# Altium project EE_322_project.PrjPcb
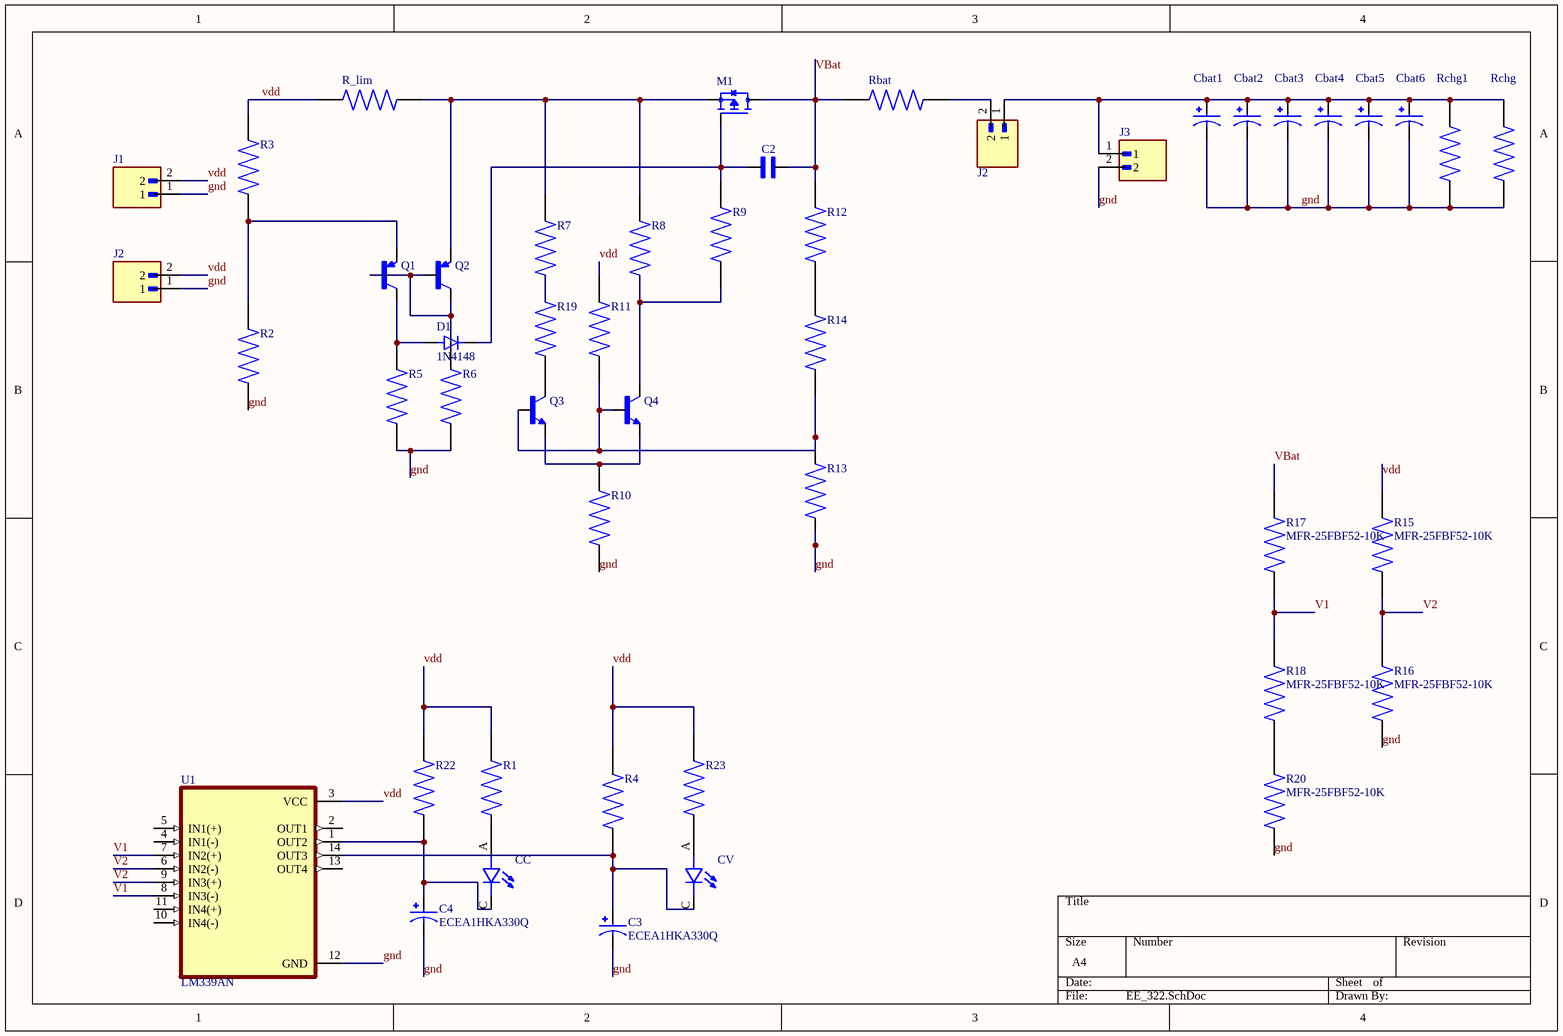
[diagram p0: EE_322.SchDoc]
1 sheet, 48 parts. Net scope: global (net labels, ports and power ports of the same name join across sheets).
Board file: EE322.PcbDoc

## Sheet EE_322.SchDoc
size A4; SheetNumber: 1; SheetTotal: 1

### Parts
(Parts that share a designator on the sheet are numbered #1, #2 ... from top to bottom, then left to right.)
C2  (no value)  [CAPRR254W50L508T317H508]
C3  ECEA1HKA330Q  [CAPPRD500W45D800H700]
C4  ECEA1HKA330Q  [CAPPRD500W45D800H700]
Cbat1  (no value)  [CAPPRD750W80D1600H3150]
Cbat2  (no value)  [CAPPRD750W80D1600H3150]
Cbat3  (no value)  [CAPPRD750W80D1600H3150]
Cbat4  (no value)  [CAPPRD750W80D1600H3150]
Cbat5  (no value)  [CAPPRD750W80D1600H3150]
Cbat6  (no value)  [CAPPRD750W80D1600H3150]
CC  (no value)  [LEDRD254W57D500H1070]
CV  (no value)  [LEDRD254W57D500H1070]
D1  1N4148  [DIOAD753W49L380D172B]
J1  (no value)  [CONNFLY_DS1021-1X2SF11-B]
J2#1  (no value)  [CONNFLY_DS1021-1X2SF11-B]
J2#2  (no value)  [CONNFLY_DS1021-1X2SF11-B]
J3  (no value)  [CONNFLY_DS1021-1X2SF11-B]
M1  (no value)  [TO254P1052X465X1989-3]
Q1  (no value)  [TO92254P460H750-3]
Q2  (no value)  [TO92254P460H750-3]
Q3  (no value)  [TO92254P460H750-3]
Q4  (no value)  [TO92254P460H750-3]
R1  (no value)  [RESAD1100W55L680D260]
R2  (no value)  [RESAD1100W55L680D260]
R3  (no value)  [RESAD1100W55L680D260]
R4  (no value)  [RESAD1100W55L680D260]
R5  (no value)  [RESAD1100W55L680D260]
R6  (no value)  [RESAD1100W55L680D260]
R7  (no value)  [RESAD1100W55L680D260]
R8  (no value)  [RESAD1100W55L680D260]
R9  (no value)  [RESAD1100W55L680D260]
R10  (no value)  [RESAD1100W55L680D260]
R11  (no value)  [RESAD1100W55L680D260]
R12  (no value)  [RESAD1100W55L680D260]
R13  (no value)  [RESAD1100W55L680D260]
R14  (no value)  [RESAD1100W55L680D260]
R15  MFR-25FBF52-10K  [RESAD1100W55L680D260]
R16  MFR-25FBF52-10K  [RESAD1100W55L680D260]
R17  MFR-25FBF52-10K  [RESAD1100W55L680D260]
R18  MFR-25FBF52-10K  [RESAD1100W55L680D260]
R19  (no value)  [RESAD1100W55L680D260]
R20  MFR-25FBF52-10K  [RESAD1100W55L680D260]
R22  (no value)  [RESAD1100W55L680D260]
R23  (no value)  [RESAD1100W55L680D260]
R_lim  (no value)  [RESAD1100W55L680D260]
Rbat  (no value)  [RESAD1100W55L680D260]
Rchg  (no value)  [RESAD1100W55L680D260]
Rchg1  (no value)  [RESAD1100W55L680D260]
U1  LM339AN  [DIP794W45P254L1969H508Q14]

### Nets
gnd: C3.N C4.N Cbat1.N Cbat2.N Cbat3.N Cbat4.N Cbat5.N Cbat6.N J1.1 J2#2.1 J3.2 R2.1 R5.1 R6.1 R10.1 R13.1 R16.1 R20.1 Rchg.1 Rchg1.1 U1.12(GND)
V1: R17.1 R18.2 U1.7(IN2(+)) U1.8(IN3(-))
V2: R15.1 R16.2 U1.6(IN2(-)) U1.9(IN3(+))
VBat: C2.2 M1.2(D) R12.2 R17.2 Rbat.2
vdd: J1.2 J2#2.2 R1.2 R3.2 R4.2 R11.2 R15.2 R22.2 R23.2 R_lim.1 U1.3(VCC)
NetC2_1: C2.1 D1.K M1.1(G) R9.2
NetC3_P: C3.P CV.C R4.1 U1.14(OUT3)
NetC4_P: C4.P CC.C R22.1 U1.1(OUT2)
NetCbat1_P: Cbat1.P Cbat2.P Cbat3.P Cbat4.P Cbat5.P Cbat6.P J2#1.1 J3.1 Rchg.2 Rchg1.2
NetCC_A: CC.A R1.1
NetCV_A: CV.A R23.1
NetD1_A: D1.A Q1.3(C) R5.2
NetJ2#1_2: J2#1.2 Rbat.1
NetM1_3: M1.3(S) Q2.1(E) R7.2 R8.2 R_lim.2
NetQ1_1: Q1.1(E) R2.2 R3.1
NetQ1_2: Q1.2(B) Q2.2(B) Q2.3(C) R6.2
NetQ3_1: Q3.1(E) Q4.1(E) R10.2
NetQ3_2: Q3.2(B) Q4.2(B) R11.1 R13.2 R14.1
NetQ3_3: Q3.3(C) R19.1
NetQ4_3: Q4.3(C) R8.1 R9.1
NetR7_1: R7.1 R19.2
NetR12_1: R12.1 R14.2
NetR18_1: R18.1 R20.2

Not connected (* = marked no-connect by the designer): U1 2(OUT1) 4(IN1(-)) 5(IN1(+)) 10(IN4(-)) 11(IN4(+)) 13(OUT4)

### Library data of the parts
C2 = SR291C104KAR: SR Series 5.08 x 5.08 mm 100 nF 100 V Â±10 % Tol. X7R Radial Lead/SkyCapÂ®; MF: AVX
C3 C4 = ECEA1HKA330Q: CAP ALUM 33UF 20% 50V RADIAL; MF: Panasonic; MP: ECE-A1HKA330Q
Cbat1-Cbat6 = ECA1HHG222: Cap Aluminum 2200uF 50V 20% (16 X 31.5mm) Radial Aluminum Cylindrical Can 7.5mm 1470mA 2000 hr 105C Bulk; MF: Panasonic
CC CV = L08R5000Q1: LED, 5MM, ORANGE; LED / Lamp Size: 5mm / T-1 3/4; LED Colour: Orange; Typ Luminous Intensity: 4.3mcd; Viewing Angle: ...; MF: LED Technology
D1 = 1N4148: Diode Standard 75V 200mA Surface Mount SOD-523F; MF: onsemi
J1 J2#1 J2#2 J3 = DS1021-1X2SF11-B: 2 position 2.54mm single row vertical pin header; MF: Connfly
M1 = IRF9540: P-Channel 100 V 19A (Tc) 3.7W (Ta), 150W (Tc) Surface Mount DÂ²PAK (TO-263); MF: Vishay
Q1 Q2 = 2N3906: BJT, TO-92, 40V, 200mA, PNP, 0.625W, 150Â°C; MF: Diotec Semiconductor
Q3 Q4 = 2N3904: BJT, TO-92, 40V, 200mA, NPN, 0.625W, 150Â°C; MF: Diotec Semiconductor
R1-R20 R22 R23 R_lim Rbat Rchg Rchg1 = MFR-25FBF52-10K: 10.2 kOhms Â±1% 0.25W, 1/4W Through Hole Resistor Axial - Metal Film; MF: Yageo
U1 = LM339AN: Precision quad differential comparator, commercial grade; MF: Texas Instruments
